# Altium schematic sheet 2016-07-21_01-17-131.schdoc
size 387 x 172 mm; SheetNumber: 1; SheetTotal: 1
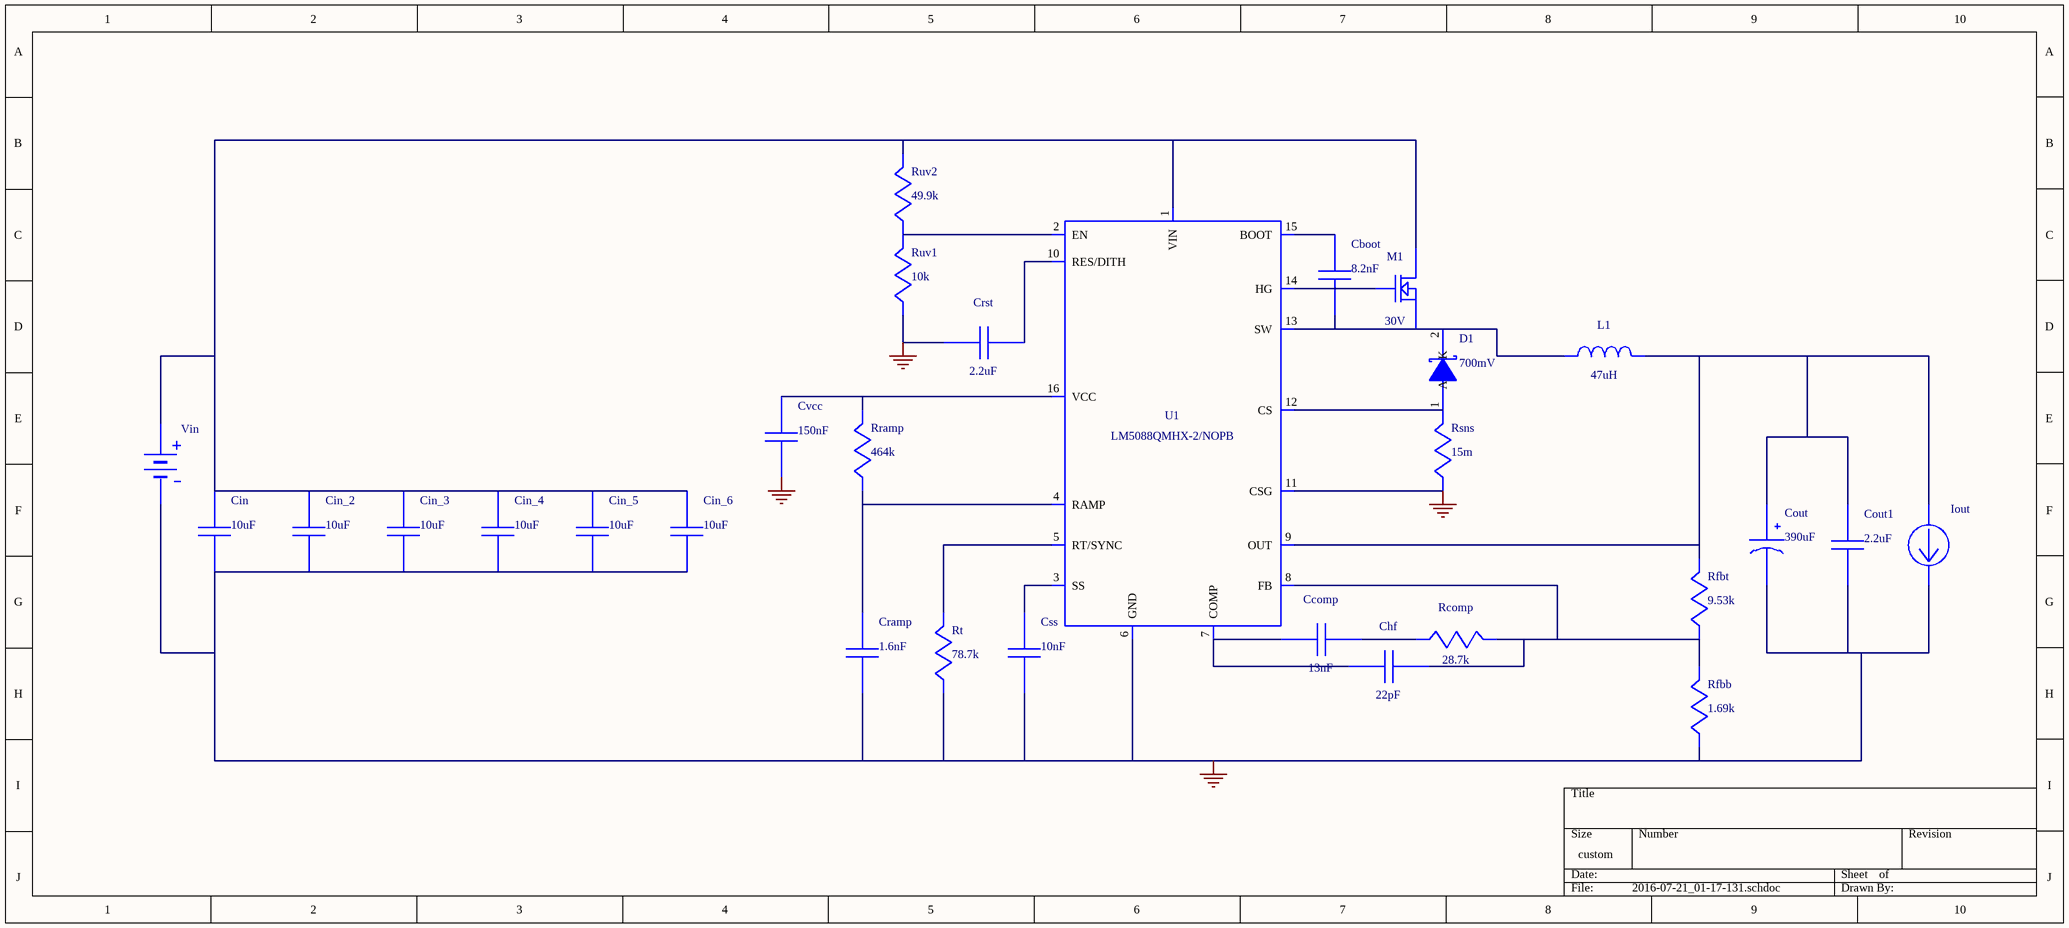
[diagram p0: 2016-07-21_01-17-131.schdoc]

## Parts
Cboot  value 8.2nF  (hidden comment: GRM033R61A822KA01D)
Ccomp  value 13nF  (hidden comment: GRM3195C1H133JA01D)
Chf  value 22pF  (hidden comment: C0603C220K3GACTU)
Cin  value 10uF  (hidden comment: GRM32ER7YA106KA12L)
Cin_2  value 10uF  (hidden comment: GRM32ER7YA106KA12L)
Cin_3  value 10uF  (hidden comment: GRM32ER7YA106KA12L)
Cin_4  value 10uF  (hidden comment: GRM32ER7YA106KA12L)
Cin_5  value 10uF  (hidden comment: GRM32ER7YA106KA12L)
Cin_6  value 10uF  (hidden comment: GRM32ER7YA106KA12L)
Cout  value 390uF  (hidden comment: 20SVPF390M)
Cout1  value 2.2uF  (hidden comment: GRM188R61A225KE34D)
Cramp  value 1.6nF  (hidden comment: GRM1885C1H162JA01D)
Crst  value 2.2uF  (hidden comment: C0603C225K9PACTU)
Css  value 10nF  (hidden comment: C0603C103J5RACTU)
Cvcc  value 150nF  (hidden comment: GRM155R60J154KE01D)
D1  value 700mV  (hidden comment: MBRB745PBF)
Iout  WB_CURRENT_LOAD  (value not drawn)
L1  value 47uH  (hidden comment: IHLP6767GZER470M11)
M1  value 30V  (hidden comment: CSD17579Q3A)
Rcomp  value 28.7k  (hidden comment: CRCW060328K7FKEA)
Rfbb  value 1.69k  (hidden comment: CRCW04021K69FKED)
Rfbt  value 9.53k  (hidden comment: CRCW04029K53FKED)
Rramp  value 464k  (hidden comment: CRCW0603464KFKEA)
Rsns  value 15m  (hidden comment: CSR1206FK15L0)
Rt  value 78.7k  (hidden comment: CRCW060378K7FKEA)
Ruv1  value 10k  (hidden comment: ERJ-6ENF1002V)
Ruv2  value 49.9k  (hidden comment: ERJ-6ENF4992V)
U1  PackageReference: LM5088QMHX-2/NOPB  (hidden comment: LM5088MHX-2/NOPB)
Vin  WB_BATTERY  (value not drawn)

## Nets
0: Cin.2 Cin_2.2 Cin_3.2 Cin_4.2 Cin_5.2 Cin_6.2 Cout.2(-) Cout1.2 Cramp.2 Crst.1 Css.2 Cvcc.2 Iout.2(-) Rfbb.2 Rsns.2 Rt.2 Ruv1.2 U1.6(GND) U1.11(CSG) U1.17(EP) Vin.2(-)
NetCboot_1: Cboot.1 D1.2(K) L1.1 M1.1(Source) M1.2(Source) M1.3(Source) U1.13(SW)
NetCboot_2: Cboot.2 U1.15(BOOT)
NetCcomp_1: Ccomp.1 Rcomp.2
NetCcomp_2: Ccomp.2 Chf.1 U1.7(COMP)
NetChf_2: Chf.2 Rcomp.1 Rfbb.1 Rfbt.2 U1.8(FB)
NetCin_1: Cin.1 Cin_2.1 Cin_3.1 Cin_4.1 Cin_5.1 Cin_6.1 M1.5(Drain) M1.6(Drain) M1.7(Drain) M1.8(Drain) M1.9(Drain) Ruv2.1 U1.1(VIN) Vin.1(+)
NetCout_1: Cout.1(+) Cout1.1 Iout.1(+) L1.2 Rfbt.1 U1.9(OUT)
NetCramp_1: Cramp.1 Rramp.2 U1.4(RAMP)
NetCrst_2: Crst.2 U1.10(RES/DITH)
NetCss_1: Css.1 U1.3(SS)
NetCvcc_1: Cvcc.1 Rramp.1 U1.16(VCC)
NetD1_1: D1.1(A) D1.3(A) Rsns.1 U1.12(CS)
NetM1_4: M1.4(Gate) U1.14(HG)
NetRt_1: Rt.1 U1.5(RT/SYNC)
NetRuv1_1: Ruv1.1 Ruv2.2 U1.2(EN)

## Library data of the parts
Cboot = GRM033R61A822KA01D: GRM033R61A822KA0; Manufacturer Name: MuRata
Ccomp = GRM3195C1H133JA01D: GRM3195C1H133JA0; Manufacturer Name: MuRata
Chf = C0603C220K3GACTU: Manufacturer Name: Kemet
Cin Cin_2-Cin_6 = GRM32ER7YA106KA12L: GRM32ER7YA106KA1; Manufacturer Name: MuRata
Cout = 20SVPF390M: Manufacturer Name: Panasonic
Cout1 = GRM188R61A225KE34D: GRM188R61A225KE3; Manufacturer Name: MuRata
Cramp = GRM1885C1H162JA01D: GRM1885C1H162JA0; Manufacturer Name: MuRata
Crst = C0603C225K9PACTU: Manufacturer Name: Kemet
Css = C0603C103J5RACTU: Manufacturer Name: Kemet
Cvcc = GRM155R60J154KE01D: GRM155R60J154KE0; Manufacturer Name: MuRata
D1 = MBRB745PBF: Manufacturer Name: Vishay-Semiconductor
L1 = IHLP6767GZER470M11: IHLP6767GZER470M; Manufacturer Name: Vishay-Dale
M1 = CSD17579Q3A: Manufacturer Name: Texas Instruments
Rcomp = CRCW060328K7FKEA: Manufacturer Name: Vishay-Dale
Rfbb = CRCW04021K69FKED: Manufacturer Name: Vishay-Dale
Rfbt = CRCW04029K53FKED: Manufacturer Name: Vishay-Dale
Rramp = CRCW0603464KFKEA: Manufacturer Name: Vishay-Dale
Rsns = CSR1206FK15L0: Manufacturer Name: Stackpole Electronics Inc
Rt = CRCW060378K7FKEA: Manufacturer Name: Vishay-Dale
Ruv1 = ERJ-6ENF1002V: Manufacturer Name: Panasonic
Ruv2 = ERJ-6ENF4992V: Manufacturer Name: Panasonic
U1 = LM5088MHX-2/NOPB: LM5088QMHX-2/NOP; Manufacturer Name: Texas Instruments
